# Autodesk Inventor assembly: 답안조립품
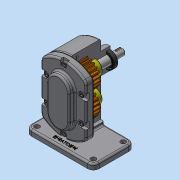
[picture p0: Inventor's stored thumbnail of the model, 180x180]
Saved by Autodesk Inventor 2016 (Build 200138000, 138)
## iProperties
Created: 2019-03
Part Number: 답안조립품
Material: 일반
Document SubType Name: Assembly
Designer: Administrator
Author: Administrator
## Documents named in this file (14)
- C:\Users\Administrator\Desktop\490307V1021\답안조립품.iam
- C:\Users\Administrator\Desktop\490307V1021\본체.ipt
- C:\Users\Administrator\Desktop\490307V1021\메인축.ipt
- C:\Users\Administrator\Desktop\490307V1021\베어링부시.ipt
- C:\Users\Administrator\Desktop\490307V1021\서브축.ipt
- C:\Users\Administrator\Desktop\490307V1021\키 6 x 6 x 18.ipt
- C:\Users\Administrator\Desktop\490307V1021\베어링부시_CPY.ipt
- C:\Users\Administrator\Desktop\490307V1021\베어링부시_CPY1.ipt
- C:\Users\Administrator\Desktop\490307V1021\베어링부시_CPY_CPY.ipt
- C:\Users\Administrator\Desktop\490307V1021\개스킷.ipt
- C:\Users\Administrator\Desktop\490307V1021\볼트 M5.ipt
- C:\Users\Administrator\Desktop\490307V1021\오일 실 16 28 7.ipt
- C:\Users\Administrator\Desktop\490307V1021\커버.ipt
- C:\Users\Administrator\Desktop\490307V1021\스퍼기어.ipt
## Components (1 placed, 1 different names)
1. 개스킷:1
